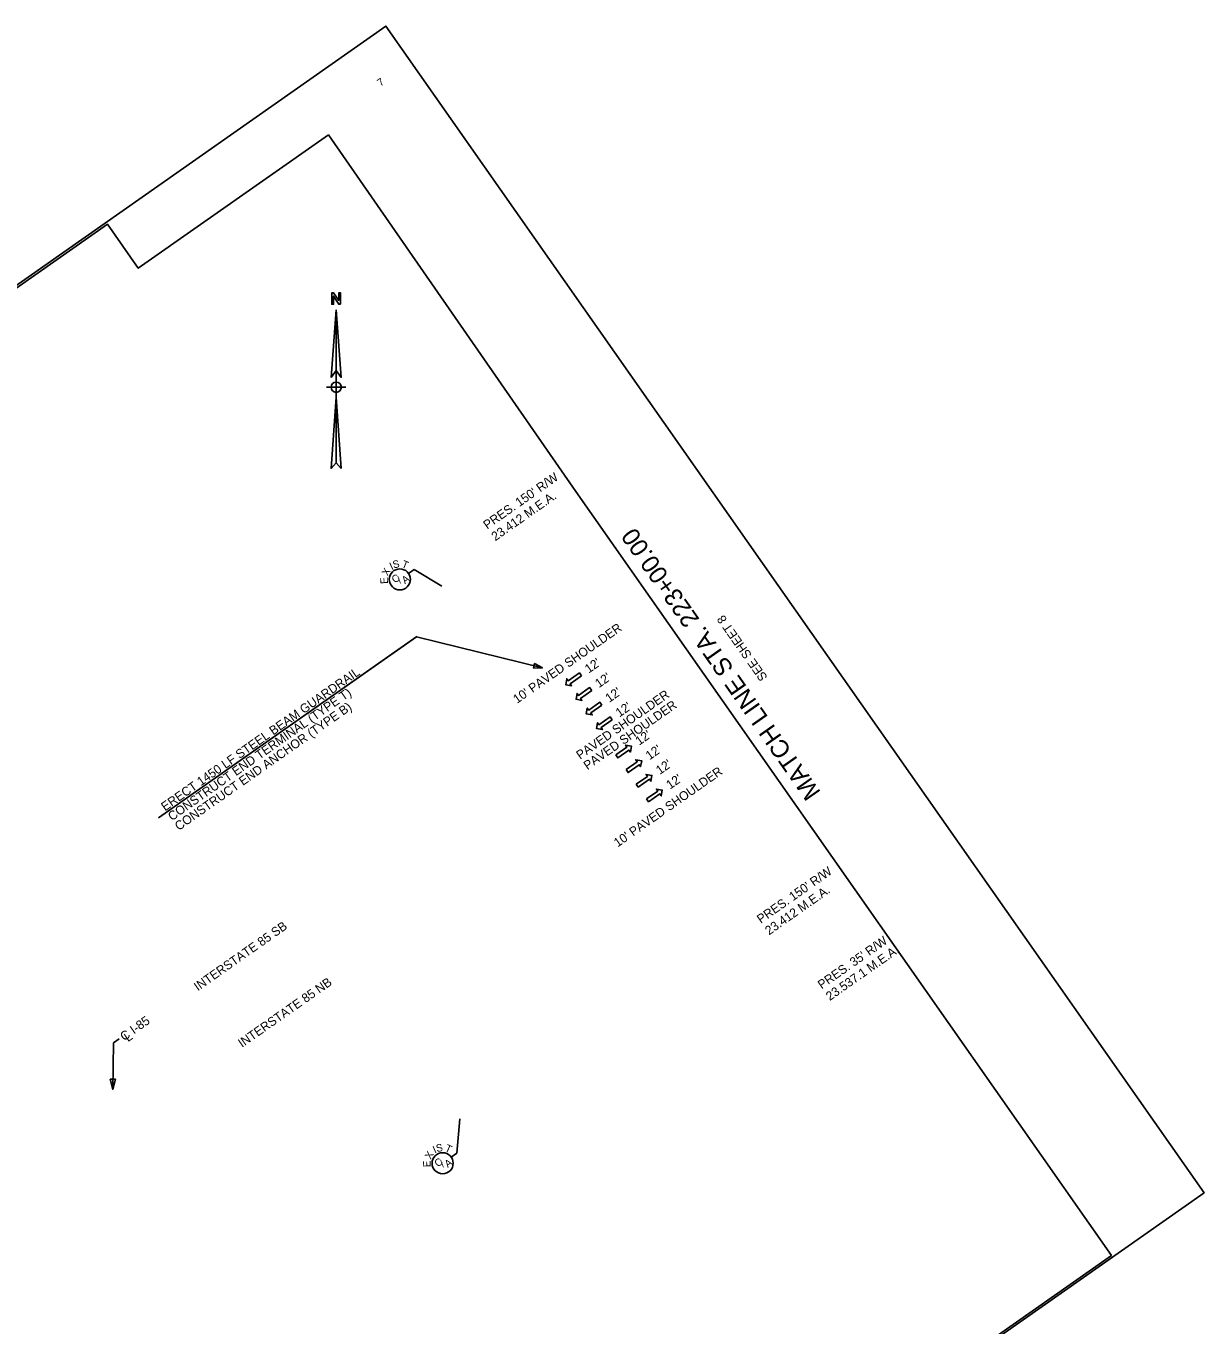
# Model space of a CAD drawing. Extents: x 1603735 to 1605655, y 1088656 to 1090462.
# Drawn here: x 1604864 to 1605655, y 1089551 to 1090423 of the extents above; entities that cross this region are included whole.
import ezdxf

# ---------------------------------------------------------------- set-up
doc = ezdxf.new("R2010")
doc.units = 0
for name, color, linetype in [('Copy of RD_HC_SUR_Bearing_TX200', 7, 'Continuous'), ('RD_EX_BldgApp', 7, 'Continuous'), ('RD_EX_Fence_Other', 7, 'Continuous'), ('RD_EX_Misc', 7, 'Continuous'), ('RD_EX_Misc_Golf_Teebox', 7, 'Continuous'), ('RD_EX_RailRoad', 7, 'Continuous'), ('RD_EX_UT', 7, 'Continuous'), ('RD_EX_VEG', 7, 'Continuous'), ('RD_HC_SUR_CL400', 7, 'Continuous'), ('TR_PM_Yellow_Solid', 7, 'Continuous')]:
    doc.layers.add(name, color=color, linetype=linetype)

msp = doc.modelspace()

# ---------------------------------------------------------------- linework, layer by layer
at = {"layer": 'Copy of RD_HC_SUR_Bearing_TX200'}
msp.add_line((1605126.86, 1090013.72), (1604953.45, 1089892.06), dxfattribs=at)
msp.add_lwpolyline([(1604953.45, 1089892.06), (1605126.58, 1090013.53), (1605211.09, 1089992.68)], dxfattribs=at)
msp.add_lwpolyline([(1605205.09, 1089992.56), (1605211.09, 1089992.68), (1605205.84, 1089995.58)], close=True, dxfattribs=at)
at = {"layer": 'RD_EX_Fence_Other'}
msp.add_lwpolyline([(1603734.73, 1089461.6), (1605106.03, 1090423.46), (1605655.3, 1089640.39), (1604284, 1088678.53)], close=True, dxfattribs=at)
at = {"layer": 'RD_EX_Misc'}
for points in [[(1605237.3, 1089987.31), (1605235.92, 1089989.28), (1605228.42, 1089984.01), (1605227.48, 1089985.35), (1605226.79, 1089981.41), (1605230.73, 1089980.71), (1605229.79, 1089982.05)], [(1605244.19, 1089977.49), (1605242.81, 1089979.45), (1605235.31, 1089974.19), (1605234.37, 1089975.52), (1605233.68, 1089971.58), (1605237.62, 1089970.89), (1605236.68, 1089972.22)], [(1605251.08, 1089967.66), (1605249.71, 1089969.63), (1605242.2, 1089964.36), (1605241.26, 1089965.7), (1605240.57, 1089961.76), (1605244.51, 1089961.06), (1605243.57, 1089962.4)], [(1605257.97, 1089957.84), (1605256.6, 1089959.8), (1605249.09, 1089954.54), (1605248.15, 1089955.87), (1605247.46, 1089951.93), (1605251.4, 1089951.24), (1605250.46, 1089952.57)], [(1605260.34, 1089934.24), (1605261.72, 1089932.28), (1605269.23, 1089937.55), (1605270.16, 1089936.21), (1605270.86, 1089940.15), (1605266.92, 1089940.84), (1605267.85, 1089939.51)], [(1605267.23, 1089924.42), (1605268.61, 1089922.46), (1605276.12, 1089927.72), (1605277.05, 1089926.39), (1605277.75, 1089930.33), (1605273.81, 1089931.02), (1605274.74, 1089929.69)], [(1605274.12, 1089914.6), (1605275.5, 1089912.63), (1605283.01, 1089917.9), (1605283.94, 1089916.56), (1605284.64, 1089920.5), (1605280.7, 1089921.2), (1605281.63, 1089919.86)], [(1605281.01, 1089904.77), (1605282.39, 1089902.81), (1605289.9, 1089908.07), (1605290.84, 1089906.74), (1605291.53, 1089910.68), (1605287.59, 1089911.37), (1605288.52, 1089910.04)]]:
    msp.add_lwpolyline(points, close=True, dxfattribs=at)
at = {"layer": 'RD_EX_RailRoad'}
for p, q in [((1605072.62, 1090232.9), (1605069.21, 1090187.59)), ((1605072.63, 1090192.24), (1605069.21, 1090187.59)), ((1605072.63, 1090192.24), (1605072.62, 1090174.4)), ((1605079.15, 1090181.02), (1605066.17, 1090181.02)), ((1605072.62, 1090174.4), (1605076.04, 1090126.56)), ((1605076.04, 1090126.56), (1605072.62, 1090130.39))]:
    msp.add_line(p, q, dxfattribs=at)
msp.add_lwpolyline([(1605075.56, 1090236.73), (1605074.33, 1090236.73), (1605070.92, 1090242.2), (1605070.92, 1090241.38), (1605070.92, 1090236.73), (1605069.69, 1090236.73), (1605069.69, 1090244.32), (1605070.92, 1090244.32), (1605074.33, 1090239.26), (1605074.33, 1090239.67), (1605074.33, 1090244.32), (1605075.56, 1090244.32), (1605075.56, 1090236.73)], dxfattribs=at)
for points in [[(1605072.62, 1090232.9), (1605076.04, 1090187.59), (1605072.63, 1090192.24)], [(1605072.62, 1090174.4), (1605072.62, 1090130.39), (1605069.21, 1090126.56)]]:
    msp.add_lwpolyline(points, close=True, dxfattribs=at)
msp.add_circle((1605072.66, 1090181.02), 3.45, dxfattribs=at)
at = {"layer": 'RD_EX_UT'}
msp.add_lwpolyline([(1605233.56, 1090111.04), (1605405.83, 1089865.44), (1605593.12, 1089598.42), (1604362.43, 1088735.18), (1604177.81, 1089004.07), (1604005.53, 1089249.68), (1603817.48, 1089517.78), (1604919.05, 1090290.45), (1604939.78, 1090260.89), (1605067.39, 1090350.4)], close=True, dxfattribs=at)
msp.add_lwpolyline([(1605233.56, 1090111.04), (1605405.83, 1089865.44), (1605593.12, 1089598.42), (1604362.43, 1088735.18), (1604177.81, 1089004.07), (1604005.53, 1089249.68), (1603817.48, 1089517.78), (1604919.05, 1090290.45), (1604939.78, 1090260.89), (1605067.39, 1090350.4)], close=True, dxfattribs=at)
msp.add_lwpolyline([(1605233.56, 1090111.04), (1605405.83, 1089865.44), (1605593.12, 1089598.42), (1604362.43, 1088735.18), (1604177.81, 1089004.07), (1604005.53, 1089249.68), (1603817.48, 1089517.78), (1604919.05, 1090290.45), (1604939.78, 1090260.89), (1605067.39, 1090350.4)], close=True, dxfattribs=at)
at = {"layer": 'RD_EX_VEG'}
msp.add_lwpolyline([(1605405.83, 1089865.44), (1605319.69, 1089988.24), (1605233.56, 1090111.04)], dxfattribs=at)
at = {"layer": 'RD_HC_SUR_CL400'}
for p, q in [((1605121.15, 1090056.12), (1605124.9, 1090058.75)), ((1605124.9, 1090058.75), (1605143.67, 1090047.56)), ((1605153.66, 1089666.92), (1605155.61, 1089690.12)), ((1605149.91, 1089664.29), (1605153.66, 1089666.92))]:
    msp.add_line(p, q, dxfattribs=at)
for centre in [(1605115.35, 1090052.05), (1605144.11, 1089660.22)]:
    msp.add_circle(centre, 7.08, dxfattribs=at)
at = {"layer": 'TR_PM_Yellow_Solid'}
msp.add_lwpolyline([(1604922.62, 1089709.72), (1604923.05, 1089741.01), (1604926.89, 1089743.7)], dxfattribs=at)
msp.add_lwpolyline([(1604924.43, 1089716.59), (1604920.99, 1089716.64), (1604922.62, 1089709.72)], close=True, dxfattribs=at)

# ---------------------------------------------------------------- texts
at = {"layer": 'Copy of RD_HC_SUR_Bearing_TX200'}
for s, p in [('ERECT 1450 LF STEEL BEAM GUARDRAIL', (1604957.74, 1089896.29)), ('CONSTRUCT END TERMINAL (TYPE T)', (1604962.34, 1089889.74)), ('CONSTRUCT END ANCHOR (TYPE B)', (1604966.93, 1089883.2))]:
    msp.add_text(s, height=6, rotation=35.05352, dxfattribs=at).set_placement(p)
at = {"layer": 'RD_EX_BldgApp'}
for s, p in [("PRES. 150' R/W", (1605174.04, 1090085.39)), ('23.412 M.E.A.', (1605179.5, 1090077.61)), ("PRES. 150' R/W", (1605357.77, 1089820.86)), ('23.412 M.E.A.', (1605363.23, 1089813.08)), ("PRES. 35' R/W", (1605398.6, 1089776.83)), ('23.537.1 M.E.A.', (1605404.05, 1089769.05))]:
    msp.add_text(s, height=6, rotation=35.04683, dxfattribs=at).set_placement(p)
at = {"layer": 'RD_EX_Misc_Golf_Teebox'}
for s, height, rotation, p in [('7', 5, 35.04683, (1605102.4, 1090382.74)), ("10' PAVED SHOULDER", 6, 35.0452, (1605194.06, 1089968.46)), ("12'", 6, 35.04357, (1605242.18, 1089988.8)), ("12'", 6, 35.04357, (1605249.07, 1089978.98)), ('PAVED SHOULDER', 6, 35.0452, (1605236.43, 1089930.95)), ("12'", 6, 35.04357, (1605255.96, 1089969.15)), ('PAVED SHOULDER', 6, 35.0452, (1605241.35, 1089923.93)), ("12'", 6, 35.04357, (1605262.85, 1089959.33)), ("12'", 6, 35.04357, (1605276.11, 1089940.42)), ("12'", 6, 35.04357, (1605283.01, 1089930.59)), ("12'", 6, 35.04357, (1605289.9, 1089920.77)), ("10' PAVED SHOULDER", 6, 35.0452, (1605261.64, 1089872.12)), ("12'", 6, 35.04357, (1605296.79, 1089910.94))]:
    msp.add_text(s, height=height, rotation=rotation, dxfattribs=at).set_placement(p)
at = {"layer": 'RD_EX_VEG'}
for s, height, rotation, p in [('MATCH LINE STA. 223+00.00', 12, 125.04683, (1605398.35, 1089909.2)), ('SEE SHEET 8', 6, 125.0981, (1605362.5, 1089986.41))]:
    msp.add_text(s, height=height, rotation=rotation, dxfattribs=at).set_placement(p)
at = {"layer": 'RD_HC_SUR_CL400'}
for s, rotation, p in [('X', 60.14035, (1605107.17, 1090054.02)), ('I', 24.97888, (1605109.8, 1090058.38)), ('S', 13.25838, (1605111.2, 1090059.37)), ('T', 338.09691, (1605116.18, 1090060.43)), ('E', 93.62747, (1605107.44, 1090049.18)), ('C', 35.04357, (1605112.01, 1090049.23)), ('/', 35.04357, (1605115.64, 1090049.2)), ('A', 35.04357, (1605118.79, 1090048.78)), ('X', 58.18819, (1605136, 1089662.47)), ('I', 23.02672, (1605138.77, 1089666.73)), ('S', 11.30623, (1605140.21, 1089667.68)), ('T', 336.14476, (1605145.22, 1089668.57)), ('E', 91.67531, (1605136.1, 1089657.62)), ('C', 35.04357, (1605140.77, 1089657.4)), ('/', 35.04357, (1605144.4, 1089657.37)), ('A', 35.04357, (1605147.54, 1089656.95))]:
    msp.add_text(s, height=5, rotation=rotation, dxfattribs=at).set_placement(p)
at = {"layer": 'TR_PM_Yellow_Solid'}
for s, p in [('INTERSTATE 85 SB', (1604979.77, 1089775.55)), ('INTERSTATE 85 NB', (1605009.42, 1089737.65)), ('C I-85', (1604930.25, 1089742.01)), ('L', (1604932.84, 1089741.41))]:
    msp.add_text(s, height=6, rotation=35.05352, dxfattribs=at).set_placement(p)

doc.saveas('drawing.dxf')
